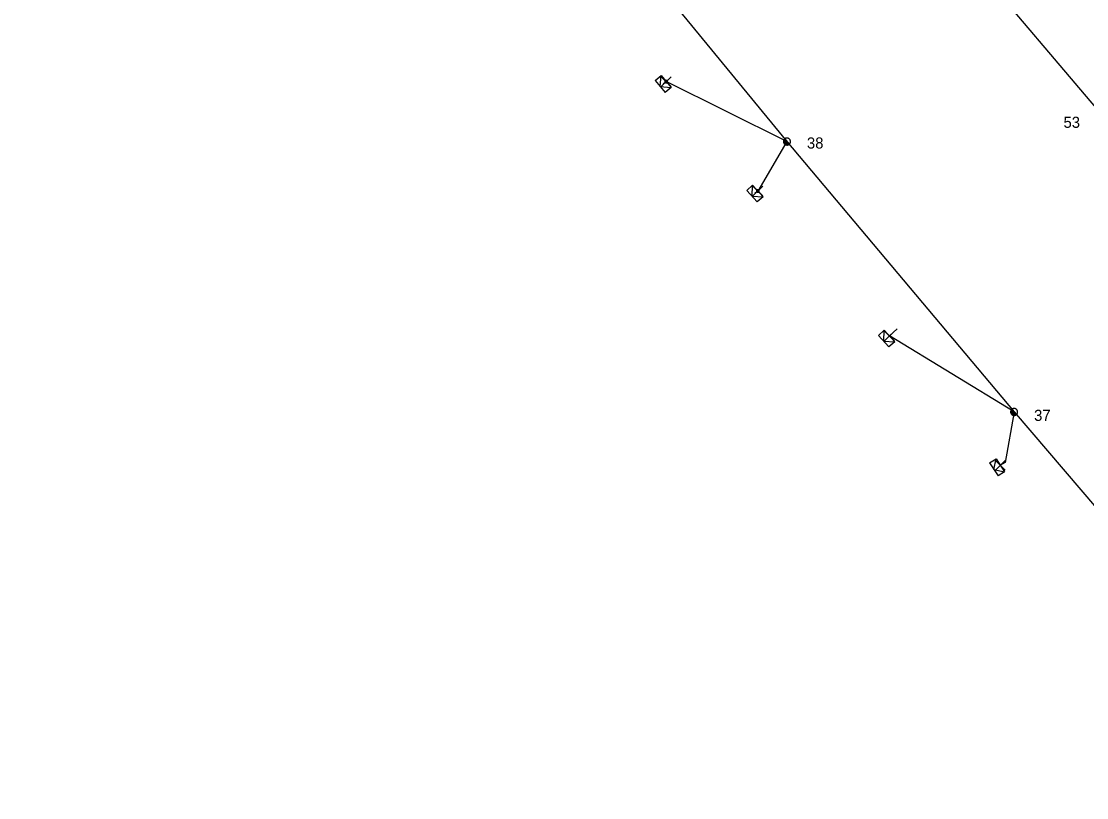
# Model space of a CAD drawing. Extents: x -536149 to -535465, y -1201639 to -1201298.
# Drawn here: x -535704.3 to -535608.3, y -1201492.5 to -1201422.6 of the extents above; entities that cross this region are included whole.
import ezdxf

# ---------------------------------------------------------------- set-up
doc = ezdxf.new("R2010")
doc.units = 0
for name, color, linetype in [('Vrstva 1', 7, 'Continuous'), ('Vrstva 13', 7, 'Continuous'), ('Vrstva 14', 7, 'Continuous'), ('Vrstva 2', 7, 'Continuous'), ('Vrstva 31', 7, 'Continuous'), ('Vrstva 34', 7, 'Continuous'), ('Vrstva 52', 7, 'Continuous'), ('Vrstva 54', 7, 'Continuous'), ('Vrstva 8', 7, 'Continuous'), ('Vrstva 9', 7, 'Continuous')]:
    doc.layers.add(name, color=color, linetype=linetype)

# ---------------------------------------------------------------- blocks, each defined once
blk = doc.blocks.new('NN440')
at = {"layer": 'Vrstva 2'}
for points in [[(0.63, 0), (0.63, 0.06), (0.62, 0.13), (0.6, 0.19), (0.58, 0.25), (0.55, 0.31), (0.51, 0.37), (0.47, 0.42), (0.42, 0.46), (0.37, 0.51), (0.32, 0.54), (0.26, 0.57), (0.2, 0.59), (0.13, 0.61), (0.07, 0.62), (0, 0.63), (-0.06, 0.62), (-0.13, 0.61), (-0.19, 0.59), (-0.26, 0.57), (-0.31, 0.54), (-0.37, 0.51), (-0.42, 0.46), (-0.47, 0.42), (-0.51, 0.37), (-0.54, 0.31), (-0.57, 0.25), (-0.6, 0.19), (-0.62, 0.13), (-0.63, 0.06), (-0.63, 0), (-0.63, -0.07), (-0.62, -0.14), (-0.6, -0.2), (-0.57, -0.26), (-0.54, -0.32), (-0.51, -0.37), (-0.47, -0.43), (-0.42, -0.47), (-0.37, -0.51), (-0.31, -0.55), (-0.26, -0.58), (-0.19, -0.6), (-0.13, -0.62), (-0.06, -0.63), (0, -0.63), (0.07, -0.63), (0.13, -0.62), (0.2, -0.6), (0.26, -0.58), (0.32, -0.55), (0.37, -0.51), (0.42, -0.47), (0.47, -0.43), (0.51, -0.37), (0.55, -0.32), (0.58, -0.26), (0.6, -0.2), (0.62, -0.14), (0.63, -0.07), (0.63, 0)], [(-0.63, 0), (0.63, 0)], [(-0.6, -0.18), (0.57, -0.18)], [(-0.51, -0.32), (0.5, -0.32)], [(-0.37, -0.47), (0.35, -0.47)]]:
    blk.add_lwpolyline(points, dxfattribs=at)
blk = doc.blocks.new('NN800')
at = {"layer": 'Vrstva 1'}
for points in [[(-0.442, 0.442), (0.442, -0.442)], [(-0.442, -0.442), (0.442, 0.442)]]:
    blk.add_lwpolyline(points, dxfattribs=at)
blk = doc.blocks.new('NN630')
at = {"layer": 'Vrstva 9'}
for points in [[(-0.003, -0.7), (-0.703, 0)], [(-0.703, -0.7), (-0.703, 0), (0.697, 0), (0.697, -0.7)], [(-0.703, -0.7), (0.697, -0.7)], [(-0.003, -0.7), (0.697, 0)]]:
    blk.add_lwpolyline(points, dxfattribs=at)
blk = doc.blocks.new('NN500')
at = {"layer": 'Vrstva 2'}
for points in [[(0, -0.24), (0.02, -0.23), (0.05, -0.23), (0.07, -0.22), (0.09, -0.22), (0.12, -0.2), (0.14, -0.19), (0.16, -0.18), (0.17, -0.16), (0.19, -0.14), (0.2, -0.12), (0.21, -0.1), (0.22, -0.07), (0.23, -0.05), (0.23, -0.02), (0.23, 0), (0.23, 0.02), (0.23, 0.05), (0.22, 0.07), (0.21, 0.1), (0.2, 0.12), (0.19, 0.14), (0.17, 0.16), (0.16, 0.17), (0.14, 0.19), (0.12, 0.2), (0.09, 0.21), (0.07, 0.22), (0.05, 0.23), (0.02, 0.23), (0, 0.23), (-0.03, 0.23), (-0.05, 0.23), (-0.07, 0.22), (-0.1, 0.21), (-0.12, 0.2), (-0.14, 0.19), (-0.16, 0.17), (-0.18, 0.16), (-0.19, 0.14), (-0.2, 0.12), (-0.22, 0.1), (-0.22, 0.07), (-0.23, 0.05), (-0.23, 0.02), (-0.24, 0), (-0.23, -0.02), (-0.23, -0.05), (-0.22, -0.07), (-0.22, -0.1), (-0.2, -0.12), (-0.19, -0.14), (-0.18, -0.16), (-0.16, -0.18), (-0.14, -0.19), (-0.12, -0.2), (-0.1, -0.22), (-0.07, -0.22), (-0.05, -0.23), (-0.03, -0.23), (0, -0.24)], [(0, -0.24), (0.02, -0.23), (0.05, -0.23), (0.07, -0.22), (0.09, -0.22), (0.12, -0.2), (0.14, -0.19), (0.16, -0.18), (0.17, -0.16), (0.19, -0.14), (0.2, -0.12), (0.21, -0.1), (0.22, -0.07), (0.23, -0.05), (0.23, -0.02), (0.23, 0), (0.23, 0.02), (0.23, 0.05), (0.22, 0.07), (0.21, 0.1), (0.2, 0.12), (0.19, 0.14), (0.17, 0.16), (0.16, 0.17), (0.14, 0.19), (0.12, 0.2), (0.09, 0.21), (0.07, 0.22), (0.05, 0.23), (0.02, 0.23), (0, 0.23), (-0.03, 0.23), (-0.05, 0.23), (-0.07, 0.22), (-0.1, 0.21), (-0.12, 0.2), (-0.14, 0.19), (-0.16, 0.17), (-0.18, 0.16), (-0.19, 0.14), (-0.2, 0.12), (-0.22, 0.1), (-0.22, 0.07), (-0.23, 0.05), (-0.23, 0.02), (-0.24, 0), (-0.23, -0.02), (-0.23, -0.05), (-0.22, -0.07), (-0.22, -0.1), (-0.2, -0.12), (-0.19, -0.14), (-0.18, -0.16), (-0.16, -0.18), (-0.14, -0.19), (-0.12, -0.2), (-0.1, -0.22), (-0.07, -0.22), (-0.05, -0.23), (-0.03, -0.23), (0, -0.24)], [(0, -0.21), (0.02, -0.2), (0.04, -0.2), (0.06, -0.2), (0.08, -0.19), (0.1, -0.18), (0.12, -0.17), (0.14, -0.15), (0.15, -0.14), (0.16, -0.12), (0.18, -0.1), (0.19, -0.08), (0.19, -0.06), (0.2, -0.04), (0.2, -0.02), (0.2, 0), (0.2, 0.02), (0.2, 0.04), (0.19, 0.06), (0.19, 0.08), (0.18, 0.1), (0.16, 0.12), (0.15, 0.14), (0.14, 0.15), (0.12, 0.17), (0.1, 0.18), (0.08, 0.19), (0.06, 0.19), (0.04, 0.2), (0.02, 0.2), (0, 0.2), (-0.02, 0.2), (-0.04, 0.2), (-0.06, 0.19), (-0.08, 0.19), (-0.1, 0.18), (-0.12, 0.17), (-0.14, 0.15), (-0.15, 0.14), (-0.17, 0.12), (-0.18, 0.1), (-0.19, 0.08), (-0.2, 0.06), (-0.2, 0.04), (-0.21, 0.02), (-0.21, 0), (-0.21, -0.02), (-0.2, -0.04), (-0.2, -0.06), (-0.19, -0.08), (-0.18, -0.1), (-0.17, -0.12), (-0.15, -0.14), (-0.14, -0.15), (-0.12, -0.17), (-0.1, -0.18), (-0.08, -0.19), (-0.06, -0.2), (-0.04, -0.2), (-0.02, -0.2), (0, -0.21)], [(0, -0.18), (0.02, -0.18), (0.04, -0.17), (0.05, -0.17), (0.07, -0.16), (0.09, -0.15), (0.1, -0.14), (0.12, -0.13), (0.13, -0.12), (0.14, -0.1), (0.15, -0.09), (0.16, -0.07), (0.17, -0.05), (0.17, -0.04), (0.17, -0.02), (0.17, 0), (0.17, 0.02), (0.17, 0.04), (0.17, 0.05), (0.16, 0.07), (0.15, 0.09), (0.14, 0.1), (0.13, 0.12), (0.12, 0.13), (0.1, 0.14), (0.09, 0.15), (0.07, 0.16), (0.05, 0.17), (0.04, 0.17), (0.02, 0.17), (0, 0.18), (-0.02, 0.17), (-0.04, 0.17), (-0.06, 0.17), (-0.07, 0.16), (-0.09, 0.15), (-0.1, 0.14), (-0.12, 0.13), (-0.13, 0.12), (-0.14, 0.1), (-0.15, 0.09), (-0.16, 0.07), (-0.17, 0.05), (-0.17, 0.04), (-0.18, 0.02), (-0.18, 0), (-0.18, -0.02), (-0.17, -0.04), (-0.17, -0.05), (-0.16, -0.07), (-0.15, -0.09), (-0.14, -0.1), (-0.13, -0.12), (-0.12, -0.13), (-0.1, -0.14), (-0.09, -0.15), (-0.07, -0.16), (-0.06, -0.17), (-0.04, -0.17), (-0.02, -0.18), (0, -0.18)], [(0, -0.15), (0.01, -0.15), (0.03, -0.14), (0.04, -0.14), (0.06, -0.13), (0.07, -0.13), (0.08, -0.12), (0.1, -0.11), (0.11, -0.1), (0.12, -0.09), (0.13, -0.07), (0.13, -0.06), (0.14, -0.05), (0.14, -0.03), (0.14, -0.02), (0.14, 0), (0.14, 0.01), (0.14, 0.03), (0.14, 0.04), (0.13, 0.06), (0.13, 0.07), (0.12, 0.09), (0.11, 0.1), (0.1, 0.11), (0.08, 0.12), (0.07, 0.13), (0.06, 0.13), (0.04, 0.14), (0.03, 0.14), (0.01, 0.14), (0, 0.15), (-0.02, 0.14), (-0.03, 0.14), (-0.05, 0.14), (-0.06, 0.13), (-0.07, 0.13), (-0.09, 0.12), (-0.1, 0.11), (-0.11, 0.1), (-0.12, 0.09), (-0.13, 0.07), (-0.13, 0.06), (-0.14, 0.04), (-0.14, 0.03), (-0.15, 0.01), (-0.15, 0), (-0.15, -0.02), (-0.14, -0.03), (-0.14, -0.05), (-0.13, -0.06), (-0.13, -0.07), (-0.12, -0.09), (-0.11, -0.1), (-0.1, -0.11), (-0.09, -0.12), (-0.07, -0.13), (-0.06, -0.13), (-0.05, -0.14), (-0.03, -0.14), (-0.02, -0.15), (0, -0.15)], [(0, -0.12), (0.01, -0.12), (0.02, -0.11), (0.03, -0.11), (0.05, -0.11), (0.06, -0.1), (0.07, -0.09), (0.08, -0.09), (0.09, -0.08), (0.09, -0.07), (0.1, -0.06), (0.11, -0.05), (0.11, -0.04), (0.11, -0.02), (0.11, -0.01), (0.12, 0), (0.11, 0.01), (0.11, 0.02), (0.11, 0.04), (0.11, 0.05), (0.1, 0.06), (0.09, 0.07), (0.09, 0.08), (0.08, 0.09), (0.07, 0.09), (0.06, 0.1), (0.05, 0.11), (0.03, 0.11), (0.02, 0.11), (0.01, 0.12), (0, 0.12), (-0.01, 0.12), (-0.03, 0.11), (-0.04, 0.11), (-0.05, 0.11), (-0.06, 0.1), (-0.07, 0.09), (-0.08, 0.09), (-0.09, 0.08), (-0.1, 0.07), (-0.1, 0.06), (-0.11, 0.05), (-0.11, 0.04), (-0.12, 0.02), (-0.12, 0.01), (-0.12, 0), (-0.12, -0.01), (-0.12, -0.02), (-0.11, -0.04), (-0.11, -0.05), (-0.1, -0.06), (-0.1, -0.07), (-0.09, -0.08), (-0.08, -0.09), (-0.07, -0.09), (-0.06, -0.1), (-0.05, -0.11), (-0.04, -0.11), (-0.03, -0.11), (-0.01, -0.12), (0, -0.12)], [(0, -0.09), (0.01, -0.09), (0.02, -0.09), (0.03, -0.08), (0.03, -0.08), (0.04, -0.08), (0.05, -0.07), (0.06, -0.07), (0.06, -0.06), (0.07, -0.05), (0.07, -0.04), (0.08, -0.04), (0.08, -0.03), (0.08, -0.02), (0.09, -0.01), (0.09, 0), (0.09, 0.01), (0.08, 0.02), (0.08, 0.03), (0.08, 0.03), (0.07, 0.04), (0.07, 0.05), (0.06, 0.06), (0.06, 0.06), (0.05, 0.07), (0.04, 0.07), (0.03, 0.08), (0.03, 0.08), (0.02, 0.08), (0.01, 0.09), (0, 0.09), (-0.01, 0.09), (-0.02, 0.08), (-0.03, 0.08), (-0.04, 0.08), (-0.04, 0.07), (-0.05, 0.07), (-0.06, 0.06), (-0.07, 0.06), (-0.07, 0.05), (-0.08, 0.04), (-0.08, 0.03), (-0.08, 0.03), (-0.09, 0.02), (-0.09, 0.01), (-0.09, 0), (-0.09, -0.01), (-0.09, -0.02), (-0.08, -0.03), (-0.08, -0.04), (-0.08, -0.04), (-0.07, -0.05), (-0.07, -0.06), (-0.06, -0.07), (-0.05, -0.07), (-0.04, -0.08), (-0.04, -0.08), (-0.03, -0.08), (-0.02, -0.09), (-0.01, -0.09), (0, -0.09)], [(0, -0.06), (0, -0.06), (0.01, -0.06), (0.02, -0.05), (0.02, -0.05), (0.03, -0.05), (0.03, -0.05), (0.04, -0.04), (0.04, -0.04), (0.05, -0.03), (0.05, -0.03), (0.05, -0.02), (0.05, -0.02), (0.05, -0.01), (0.06, -0.01), (0.06, 0), (0.06, 0.01), (0.05, 0.01), (0.05, 0.02), (0.05, 0.02), (0.05, 0.03), (0.05, 0.03), (0.04, 0.04), (0.04, 0.04), (0.03, 0.05), (0.03, 0.05), (0.02, 0.05), (0.02, 0.05), (0.01, 0.06), (0, 0.06), (0, 0.06), (-0.01, 0.06), (-0.01, 0.06), (-0.02, 0.05), (-0.02, 0.05), (-0.03, 0.05), (-0.03, 0.05), (-0.04, 0.04), (-0.04, 0.04), (-0.05, 0.03), (-0.05, 0.03), (-0.05, 0.02), (-0.06, 0.02), (-0.06, 0.01), (-0.06, 0.01), (-0.06, 0), (-0.06, -0.01), (-0.06, -0.01), (-0.06, -0.02), (-0.05, -0.02), (-0.05, -0.03), (-0.05, -0.03), (-0.04, -0.04), (-0.04, -0.04), (-0.03, -0.05), (-0.03, -0.05), (-0.02, -0.05), (-0.02, -0.05), (-0.01, -0.06), (-0.01, -0.06), (0, -0.06)], [(0, -0.03), (0, -0.03), (0, -0.03), (0.01, -0.03), (0.01, -0.03), (0.01, -0.02), (0.02, -0.02), (0.02, -0.02), (0.02, -0.02), (0.02, -0.02), (0.02, -0.01), (0.02, -0.01), (0.03, -0.01), (0.03, -0.01), (0.03, 0), (0.03, 0), (0.03, 0), (0.03, 0.01), (0.03, 0.01), (0.02, 0.01), (0.02, 0.01), (0.02, 0.02), (0.02, 0.02), (0.02, 0.02), (0.02, 0.02), (0.01, 0.02), (0.01, 0.02), (0.01, 0.03), (0, 0.03), (0, 0.03), (0, 0.03), (0, 0.03), (-0.01, 0.03), (-0.01, 0.03), (-0.01, 0.02), (-0.02, 0.02), (-0.02, 0.02), (-0.02, 0.02), (-0.02, 0.02), (-0.02, 0.02), (-0.03, 0.01), (-0.03, 0.01), (-0.03, 0.01), (-0.03, 0.01), (-0.03, 0), (-0.03, 0), (-0.03, 0), (-0.03, -0.01), (-0.03, -0.01), (-0.03, -0.01), (-0.03, -0.01), (-0.02, -0.02), (-0.02, -0.02), (-0.02, -0.02), (-0.02, -0.02), (-0.02, -0.02), (-0.01, -0.03), (-0.01, -0.03), (-0.01, -0.03), (0, -0.03), (0, -0.03)], [(0.23, 0), (0.7, 0)]]:
    blk.add_lwpolyline(points, dxfattribs=at)
blk = doc.blocks.new('NN510')
at = {"layer": 'Vrstva 2'}
blk.add_lwpolyline([(0.001, 0.002), (0.001, 0.939)], dxfattribs=at)

msp = doc.modelspace()

# ---------------------------------------------------------------- linework, layer by layer
at = {"layer": 'Vrstva 1'}
for points in [[(-535704.28, -1201335.78), (-535687.29, -1201370.27), (-535663.05, -1201399.63), (-535635.32, -1201433.41), (-535614.862, -1201457.774), (-535589.24, -1201487.744), (-535570.255, -1201520.699), (-535562.055, -1201543.241)], [(-535566.21, -1201489.133), (-535573.362, -1201479.314), (-535581.292, -1201468.256), (-535583.925, -1201464.639), (-535590.303, -1201455.917), (-535602.568, -1201439.045), (-535607.499, -1201430.342), (-535618.17, -1201417.757), (-535627.799, -1201404.564)]]:
    msp.add_lwpolyline(points, dxfattribs=at)
at = {"layer": 'Vrstva 52'}
msp.add_lwpolyline([(-535614.862, -1201457.774), (-535615.666, -1201462.339), (-535616.098, -1201462.586)], dxfattribs=at)
at = {"layer": 'Vrstva 54'}
for points in [[(-535635.32, -1201433.41), (-535646.194, -1201428.014)], [(-535614.862, -1201457.774), (-535626.087, -1201450.934)]]:
    msp.add_lwpolyline(points, dxfattribs=at)
at = {"layer": 'Vrstva 8'}
msp.add_lwpolyline([(-535635.32, -1201433.41), (-535637.943, -1201437.87)], dxfattribs=at)

# ---------------------------------------------------------------- block references
at = {"layer": 'Vrstva 13'}
for name, p, xscale, yscale, rotation in [('NN500', (-535646.194, -1201428.014), 0.5000000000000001, 0.5, -140.7149999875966), ('NN440', (-535635.32, -1201433.41), 0.49999999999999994, 0.5000000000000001, -49.93583344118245), ('NN500', (-535637.943, -1201437.87), 0.5, 0.5, -137.79200000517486), ('NN440', (-535614.862, -1201457.774), 0.5, 0.5, -49.47215274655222)]:
    msp.add_blockref(name, p, dxfattribs=dict(at, xscale=xscale, yscale=yscale, rotation=rotation))
at = {"layer": 'Vrstva 13', "rotation": -47.640091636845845}
msp.add_blockref('NN510', (-535626.088, -1201450.934), dxfattribs=at)
at = {"layer": 'Vrstva 31'}
for p, rotation in [((-535646.194, -1201428.014), -50.7410805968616), ((-535637.943, -1201437.87), -47.81139998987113), ((-535626.087, -1201450.934), -47.63102774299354), ((-535616.098, -1201462.586), -57.30592490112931)]:
    msp.add_blockref('NN630', p, dxfattribs=dict(at, rotation=rotation))
at = {"layer": 'Vrstva 34'}
for p in [(-535646.194, -1201428.014), (-535637.943, -1201437.87), (-535626.087, -1201450.934), (-535616.098, -1201462.586)]:
    msp.add_blockref('NN800', p, dxfattribs=at)

# ---------------------------------------------------------------- texts
at = {"layer": 'Vrstva 14'}
for s, p in [('53', (-535610.41, -1201432.177)), ('38', (-535633.519, -1201434.043)), ('37', (-535613.062, -1201458.585))]:
    msp.add_text(s, height=1, dxfattribs=at).set_placement(p)

doc.saveas('drawing.dxf')
